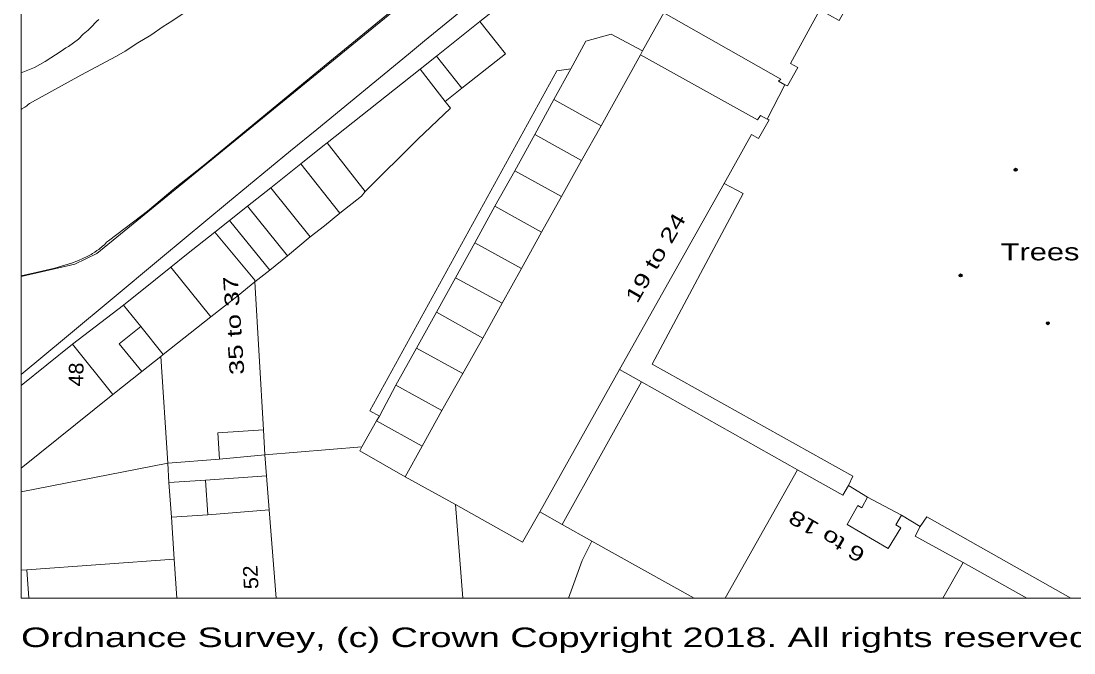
# Model space of a CAD drawing. Extents: x 528790 to 529292, y 179350 to 179856.
# Drawn here: x 528790.2 to 528898.3, y 179350.4 to 179415.2 of the extents above; entities that cross this region are included whole.
import ezdxf

# ---------------------------------------------------------------- set-up
doc = ezdxf.new("R2010")
doc.units = 0
doc.header["$LTSCALE"] = 0.6
doc.header["$PDMODE"] = 32
doc.header["$PDSIZE"] = 0.3
for name, color, linetype, lineweight in [('1', 7, 'Continuous', 13), ('2', 7, 'Continuous', 13), ('7', 7, 'Continuous', 13)]:
    doc.layers.add(name, color=color, linetype=linetype, lineweight=lineweight)
for name, color, linetype in [('3', 7, 'Continuous'), ('5', 7, 'Continuous'), ('8', 7, 'Continuous')]:
    doc.layers.add(name, color=color, linetype=linetype)

msp = doc.modelspace()

# ---------------------------------------------------------------- linework, layer by layer
at = {"layer": '1'}
for points in [[(528790.22, 179436.319), (528790.22, 179389.043), (528795.75, 179390.3), (528798, 179391.4), (528866.2, 179447.15)], [(528866.2, 179447.15), (528798, 179391.4), (528795.75, 179390.3), (528790.22, 179389.043), (528790.22, 179378.975), (528794.89, 179382.86), (528799.97, 179387.09), (528803.9, 179390.36), (528804.75, 179391.06), (528811.4, 179396.6), (528817.89, 179401.93), (528820.57, 179404.13), (528829.99, 179411.87), (528831.62, 179413.21), (528839.4, 179419.6)], [(528790.22, 179435.924), (528790.22, 179409.925), (528791.6, 179410.5), (528792.7, 179411.1), (528794.35, 179412.15), (528794.8, 179412.5), (528795.1, 179412.65), (528796.1, 179413.4), (528796.6, 179413.9), (528797.1, 179414.3), (528797.6, 179414.8), (528797.8, 179415.05), (528798, 179415.25), (528798.2, 179415.4)], [(528901.688, 179417.809), (528881.8, 179429), (528874.2, 179415.3), (528872.2, 179416.4), (528869.2, 179410.9), (528869.95, 179410.5), (528868.9, 179408.6), (528868.6, 179408.7), (528866.8, 179405.2), (528867, 179405.1), (528865.9, 179403.2), (528865.2, 179403.6), (528862.4, 179398.6), (528864.35, 179397.55), (528855, 179380.05), (528875.6, 179368.55), (528875.15, 179367.6), (528877.1, 179366.4), (528880.6, 179364.55), (528882.5, 179363.4), (528883.2, 179364.4), (528897.956, 179356.024), (528905.826, 179356.024)], [(528839.4, 179419.6), (528831.62, 179413.21), (528829.99, 179411.87), (528820.57, 179404.13), (528817.89, 179401.93), (528811.4, 179396.6), (528804.75, 179391.06), (528803.9, 179390.36), (528799.97, 179387.09), (528794.89, 179382.86), (528790.22, 179378.975), (528790.22, 179377.863), (528795.5, 179382.1), (528800.75, 179386.1), (528804.01, 179388.72), (528805.6, 179390), (528807.2, 179391.3), (528810.1, 179393.6), (528811.6, 179394.8), (528813.45, 179396.25), (528815.85, 179398.15), (528818.95, 179400.6), (528821.2, 179402.4), (528821.65, 179402.75), (528831.2, 179410.3), (528832.85, 179411.65), (528837.3, 179415.2), (528842.1, 179419)], [(528842.1, 179419), (528837.3, 179415.2), (528839.95, 179411.9), (528835.45, 179408.35), (528833.75, 179407), (528834.3, 179406.3), (528830.95, 179403.15), (528825.55, 179397.75), (528825.15, 179397.3), (528822.95, 179395.55), (528821.35, 179394.25), (528819.9, 179393.1), (528817.55, 179391.15), (528815.75, 179389.7), (528814.2, 179388.5), (528815.1, 179373.3), (528815.25, 179370.75), (528825.2, 179371.55), (528826.7, 179374.25), (528827, 179374.7), (528826, 179375.25), (528845.2, 179410.15), (528846.65, 179410.35), (528848.2, 179413.2), (528850.8, 179413.9), (528854, 179412.2), (528856.05, 179415.85)], [(528808.55, 179417.15), (528805.7, 179415.25), (528804.8, 179414.7), (528803.55, 179413.8), (528802.2, 179413), (528800.9, 179412.15), (528800, 179411.65), (528796.35, 179409.7), (528791.1, 179406.8), (528790.95, 179406.7), (528790.8, 179406.55), (528790.6, 179406.4), (528790.3, 179406.25), (528790.22, 179406.19), (528790.22, 179389.112), (528791.9, 179389.5), (528793.7, 179389.9), (528795.4, 179390.4), (528796.1, 179390.7), (528797, 179391.1), (528797.4, 179391.3), (528797.55, 179391.4), (528797.8, 179391.55), (528798, 179391.7), (528798.2, 179391.8), (528798.6, 179392.2), (528798.8, 179392.3), (528799, 179392.55), (528799.2, 179392.7), (528802.6, 179395.3), (528803.2, 179395.75), (528806, 179398.1), (528808.9, 179400.4), (528815.3, 179405.65), (528821.55, 179410.8), (528828.9, 179416.8)]]:
    msp.add_lwpolyline(points, dxfattribs=at)
for points in [[(528868.6, 179408.7), (528868.9, 179408.6), (528869.95, 179410.5), (528869.2, 179410.9), (528872.2, 179416.4), (528881.65, 179433.45), (528869.8, 179440.05), (528869.6, 179440.3), (528865.45, 179432.8), (528864.9, 179431.8), (528863.6, 179429.4), (528862.95, 179428.25), (528862.35, 179427.15), (528860.2, 179423.3), (528856.2, 179416.1), (528868.2, 179409.3), (528867.95, 179409.1)], [(528853.8, 179411.8), (528865.8, 179405.1), (528866.1, 179405.55), (528866.8, 179405.2), (528868.6, 179408.7), (528867.95, 179409.1), (528868.2, 179409.3), (528856.2, 179416.1), (528856.05, 179415.85), (528854, 179412.2)], [(528837.3, 179415.2), (528832.85, 179411.65), (528835.45, 179408.35), (528839.95, 179411.9)], [(528853.8, 179411.8), (528854, 179412.2), (528850.8, 179413.9), (528848.2, 179413.2), (528846.65, 179410.35), (528844.9, 179407.2), (528849.75, 179404.5)], [(528841.6, 179389.85), (528839.6, 179386.3), (528837.6, 179382.7), (528835.55, 179379.1), (528833.4, 179375.3), (528831.4, 179371.65), (528829.65, 179368.5), (528834.8, 179365.65), (528841.7, 179361.8), (528843.45, 179364.9), (528851.65, 179379.5), (528862.4, 179398.6), (528865.2, 179403.6), (528865.9, 179403.2), (528867, 179405.1), (528866.8, 179405.2), (528866.1, 179405.55), (528865.8, 179405.1), (528853.8, 179411.8), (528849.75, 179404.5), (528847.75, 179400.95), (528845.7, 179397.25), (528843.65, 179393.6)], [(528831.2, 179410.3), (528833.75, 179407), (528835.45, 179408.35), (528832.85, 179411.65)], [(528821.65, 179402.75), (528825.55, 179397.75), (528830.95, 179403.15), (528834.3, 179406.3), (528833.75, 179407), (528831.2, 179410.3)], [(528834.8, 179388.9), (528836.8, 179392.5), (528838.85, 179396.25), (528840.9, 179399.9), (528842.95, 179403.6), (528844.9, 179407.2), (528846.65, 179410.35), (528845.2, 179410.15), (528826, 179375.25), (528827, 179374.7), (528828.7, 179377.9), (528830.8, 179381.7), (528832.85, 179385.4)], [(528844.9, 179407.2), (528842.95, 179403.6), (528847.75, 179400.95), (528849.75, 179404.5)], [(528847.75, 179400.95), (528842.95, 179403.6), (528840.9, 179399.9), (528845.7, 179397.25)], [(528825.55, 179397.75), (528821.65, 179402.75), (528821.2, 179402.4), (528818.95, 179400.6), (528822.95, 179395.55), (528825.15, 179397.3)], [(528822.95, 179395.55), (528818.95, 179400.6), (528815.85, 179398.15), (528819.9, 179393.1), (528821.35, 179394.25)], [(528845.7, 179397.25), (528840.9, 179399.9), (528838.85, 179396.25), (528843.65, 179393.6)], [(528813.45, 179396.25), (528817.55, 179391.15), (528819.9, 179393.1), (528815.85, 179398.15)], [(528851.65, 179379.5), (528853.9, 179378.25), (528869.9, 179369.2), (528874.55, 179366.6), (528875.15, 179367.6), (528875.6, 179368.55), (528855, 179380.05), (528864.35, 179397.55), (528862.4, 179398.6)], [(528811.6, 179394.8), (528815.75, 179389.7), (528817.55, 179391.15), (528813.45, 179396.25)], [(528843.65, 179393.6), (528838.85, 179396.25), (528836.8, 179392.5), (528841.6, 179389.85)], [(528810.1, 179393.6), (528814.2, 179388.65), (528814.2, 179388.5), (528815.75, 179389.7), (528811.6, 179394.8)], [(528805.6, 179390), (528809.7, 179384.9), (528812.5, 179387.1), (528814.2, 179388.5), (528814.2, 179388.65), (528810.1, 179393.6), (528807.2, 179391.3)], [(528841.6, 179389.85), (528836.8, 179392.5), (528834.8, 179388.9), (528839.6, 179386.3)], [(528809.7, 179384.9), (528805.6, 179390), (528804.01, 179388.72), (528800.75, 179386.1), (528802.5, 179383.9), (528804.8, 179381.05)], [(528810.6, 179370.3), (528810.4, 179373), (528815.1, 179373.3), (528814.2, 179388.5), (528812.5, 179387.1), (528809.7, 179384.9), (528804.8, 179381.05), (528804.55, 179380.85), (528805.3, 179369.9)], [(528832.85, 179385.4), (528837.6, 179382.7), (528839.6, 179386.3), (528834.8, 179388.9)], [(528802.6, 179379.3), (528800.3, 179382.15), (528802.5, 179383.9), (528800.75, 179386.1), (528795.5, 179382.1), (528799.65, 179376.95)], [(528837.6, 179382.7), (528832.85, 179385.4), (528830.8, 179381.7), (528835.55, 179379.1)], [(528804.8, 179381.05), (528802.5, 179383.9), (528800.3, 179382.15), (528802.6, 179379.3), (528804.55, 179380.85)], [(528790.22, 179377.863), (528790.22, 179369.383), (528799.65, 179376.95), (528795.5, 179382.1)], [(528790.22, 179366.934), (528805.3, 179369.9), (528804.55, 179380.85), (528802.6, 179379.3), (528799.65, 179376.95), (528790.22, 179369.383)], [(528835.55, 179379.1), (528830.8, 179381.7), (528828.7, 179377.9), (528833.4, 179375.3)], [(528843.45, 179364.9), (528845.75, 179363.6), (528853.9, 179378.25), (528851.65, 179379.5)], [(528828.7, 179377.9), (528827, 179374.7), (528826.7, 179374.25), (528831.4, 179371.65), (528833.4, 179375.3)], [(528859.31, 179356.024), (528862.494, 179356.024), (528869.9, 179369.2), (528853.9, 179378.25), (528845.75, 179363.6), (528848.8, 179361.9)], [(528815.25, 179370.75), (528815.1, 179373.3), (528810.4, 179373), (528810.6, 179370.3)], [(528831.4, 179371.65), (528826.7, 179374.25), (528825.2, 179371.55), (528825, 179371.15), (528829.65, 179368.5)], [(528816.418, 179356.024), (528835.563, 179356.024), (528834.8, 179365.65), (528829.65, 179368.5), (528825, 179371.15), (528825.2, 179371.55), (528815.25, 179370.75), (528815.4, 179368.6), (528815.7, 179365.1)], [(528805.3, 179369.9), (528805.4, 179367.9), (528809.15, 179368.15), (528815.4, 179368.6), (528815.25, 179370.75), (528810.6, 179370.3)], [(528790.22, 179366.934), (528790.22, 179358.915), (528790.8, 179358.95), (528805.95, 179360.05), (528805.65, 179364.35), (528805.4, 179367.9), (528805.3, 179369.9)], [(528862.494, 179356.024), (528884.841, 179356.024), (528886.9, 179359.7), (528882, 179362.4), (528882.5, 179363.4), (528880.6, 179364.55), (528880, 179363.55), (528880.5, 179363.25), (528879.2, 179361.15), (528875, 179363.6), (528876.1, 179365.55), (528876.5, 179365.3), (528877.1, 179366.4), (528875.15, 179367.6), (528874.55, 179366.6), (528869.9, 179369.2)], [(528809.4, 179364.6), (528809.15, 179368.15), (528805.4, 179367.9), (528805.65, 179364.35)], [(528815.4, 179368.6), (528809.15, 179368.15), (528809.4, 179364.6), (528815.7, 179365.1)], [(528880.6, 179364.55), (528877.1, 179366.4), (528876.5, 179365.3), (528876.1, 179365.55), (528875, 179363.6), (528879.2, 179361.15), (528880.5, 179363.25), (528880, 179363.55)], [(528816.418, 179356.024), (528815.7, 179365.1), (528809.4, 179364.6), (528805.65, 179364.35), (528805.95, 179360.05), (528806.195, 179356.024)], [(528846.412, 179356.024), (528847.8, 179359.9), (528848.8, 179361.9), (528845.75, 179363.6), (528843.45, 179364.9), (528841.7, 179361.8), (528834.8, 179365.65), (528835.563, 179356.024)], [(528893.463, 179356.024), (528897.956, 179356.024), (528883.2, 179364.4), (528882.5, 179363.4), (528882, 179362.4), (528886.9, 179359.7)], [(528859.31, 179356.024), (528848.8, 179361.9), (528847.8, 179359.9), (528846.412, 179356.024)], [(528791.01, 179356.024), (528806.195, 179356.024), (528805.95, 179360.05), (528790.8, 179358.95)], [(528893.463, 179356.024), (528886.9, 179359.7), (528884.841, 179356.024)], [(528791.01, 179356.024), (528790.8, 179358.95), (528790.22, 179358.915), (528790.22, 179356.024)]]:
    msp.add_lwpolyline(points, close=True, dxfattribs=at)
at = {"layer": '2'}
for p, q in [((528837.3, 179415.2), (528842.1, 179419)), ((528854, 179412.2), (528856.05, 179415.85)), ((528837.3, 179415.2), (528832.85, 179411.65)), ((528854, 179412.2), (528853.8, 179411.8)), ((528832.85, 179411.65), (528831.2, 179410.3)), ((528832.85, 179411.65), (528835.45, 179408.35)), ((528849.75, 179404.5), (528853.8, 179411.8)), ((528831.2, 179410.3), (528821.65, 179402.75)), ((528831.2, 179410.3), (528833.75, 179407)), ((528844.9, 179407.2), (528846.65, 179410.35)), ((528833.75, 179407), (528835.45, 179408.35)), ((528866.8, 179405.2), (528868.6, 179408.7)), ((528842.95, 179403.6), (528844.9, 179407.2)), ((528849.75, 179404.5), (528844.9, 179407.2)), ((528840.9, 179399.9), (528842.95, 179403.6)), ((528842.95, 179403.6), (528847.75, 179400.95)), ((528847.75, 179400.95), (528849.75, 179404.5)), ((528821.65, 179402.75), (528825.55, 179397.75)), ((528818.95, 179400.6), (528815.85, 179398.15)), ((528818.95, 179400.6), (528822.95, 179395.55)), ((528845.7, 179397.25), (528847.75, 179400.95)), ((528838.85, 179396.25), (528840.9, 179399.9)), ((528845.7, 179397.25), (528840.9, 179399.9)), ((528815.85, 179398.15), (528813.45, 179396.25)), ((528815.85, 179398.15), (528819.9, 179393.1)), ((528862.4, 179398.6), (528851.65, 179379.5)), ((528843.65, 179393.6), (528845.7, 179397.25)), ((528813.45, 179396.25), (528811.6, 179394.8)), ((528813.45, 179396.25), (528817.55, 179391.15)), ((528836.8, 179392.5), (528838.85, 179396.25)), ((528838.85, 179396.25), (528843.65, 179393.6)), ((528811.6, 179394.8), (528810.1, 179393.6)), ((528811.6, 179394.8), (528815.75, 179389.7)), ((528817.55, 179391.15), (528819.9, 179393.1)), ((528841.6, 179389.85), (528843.65, 179393.6)), ((528834.8, 179388.9), (528836.8, 179392.5)), ((528841.6, 179389.85), (528836.8, 179392.5)), ((528815.75, 179389.7), (528817.55, 179391.15)), ((528805.6, 179390), (528809.7, 179384.9)), ((528814.2, 179388.5), (528815.75, 179389.7)), ((528839.6, 179386.3), (528841.6, 179389.85)), ((528814.2, 179388.5), (528815.1, 179373.3)), ((528832.85, 179385.4), (528834.8, 179388.9)), ((528834.8, 179388.9), (528839.6, 179386.3)), ((528837.6, 179382.7), (528839.6, 179386.3)), ((528795.5, 179382.1), (528800.75, 179386.1)), ((528802.5, 179383.9), (528800.75, 179386.1)), ((528830.8, 179381.7), (528832.85, 179385.4)), ((528837.6, 179382.7), (528832.85, 179385.4)), ((528804.8, 179381.05), (528809.7, 179384.9)), ((528804.8, 179381.05), (528802.5, 179383.9)), ((528790.22, 179377.863), (528795.5, 179382.1)), ((528795.5, 179382.1), (528799.65, 179376.95)), ((528835.55, 179379.1), (528837.6, 179382.7)), ((528804.55, 179380.85), (528802.6, 179379.3)), ((528804.8, 179381.05), (528804.55, 179380.85)), ((528804.55, 179380.85), (528805.3, 179369.9)), ((528828.7, 179377.9), (528830.8, 179381.7)), ((528830.8, 179381.7), (528835.55, 179379.1)), ((528802.6, 179379.3), (528799.65, 179376.95)), ((528833.4, 179375.3), (528835.55, 179379.1)), ((528851.65, 179379.5), (528843.45, 179364.9)), ((528851.65, 179379.5), (528853.9, 179378.25)), ((528827, 179374.7), (528828.7, 179377.9)), ((528833.4, 179375.3), (528828.7, 179377.9)), ((528853.9, 179378.25), (528845.75, 179363.6)), ((528853.9, 179378.25), (528869.9, 179369.2)), ((528799.65, 179376.95), (528790.22, 179369.383)), ((528826.7, 179374.25), (528827, 179374.7)), ((528831.4, 179371.65), (528833.4, 179375.3)), ((528815.1, 179373.3), (528815.25, 179370.75)), ((528825.2, 179371.55), (528826.7, 179374.25)), ((528826.7, 179374.25), (528831.4, 179371.65)), ((528815.25, 179370.75), (528825.2, 179371.55)), ((528829.65, 179368.5), (528831.4, 179371.65)), ((528805.3, 179369.9), (528810.6, 179370.3)), ((528810.6, 179370.3), (528815.25, 179370.75)), ((528815.4, 179368.6), (528815.25, 179370.75)), ((528790.22, 179366.934), (528805.3, 179369.9)), ((528805.3, 179369.9), (528805.4, 179367.9)), ((528869.9, 179369.2), (528862.494, 179356.024)), ((528805.4, 179367.9), (528809.15, 179368.15)), ((528805.4, 179367.9), (528805.65, 179364.35)), ((528809.15, 179368.15), (528815.4, 179368.6)), ((528809.15, 179368.15), (528809.4, 179364.6)), ((528815.7, 179365.1), (528815.4, 179368.6)), ((528834.8, 179365.65), (528829.65, 179368.5)), ((528875.15, 179367.6), (528877.1, 179366.4)), ((528877.1, 179366.4), (528880.6, 179364.55)), ((528809.4, 179364.6), (528815.7, 179365.1)), ((528816.418, 179356.024), (528815.7, 179365.1)), ((528834.8, 179365.65), (528835.563, 179356.024)), ((528845.75, 179363.6), (528843.45, 179364.9)), ((528805.65, 179364.35), (528809.4, 179364.6)), ((528805.65, 179364.35), (528805.95, 179360.05)), ((528848.8, 179361.9), (528845.75, 179363.6)), ((528880.6, 179364.55), (528882.5, 179363.4)), ((528859.31, 179356.024), (528848.8, 179361.9)), ((528805.95, 179360.05), (528790.8, 179358.95)), ((528805.95, 179360.05), (528806.195, 179356.024)), ((528886.9, 179359.7), (528884.841, 179356.024)), ((528886.9, 179359.7), (528893.463, 179356.024)), ((528790.8, 179358.95), (528790.22, 179358.915)), ((528791.01, 179356.024), (528790.8, 179358.95))]:
    msp.add_line(p, q, dxfattribs=at)
for points in [[(528906.55, 179446.2), (528898.1, 179448.9), (528889.7, 179451.6), (528884.6, 179453.25), (528882.9, 179453.7), (528881.15, 179454), (528880.3, 179454.1), (528879.5, 179454.15), (528878.6, 179454.2), (528877.8, 179454.15), (528876.8, 179453.9), (528875.8, 179453.7), (528874.9, 179453.3), (528873.2, 179452.55), (528871.6, 179451.55), (528870.2, 179450.55), (528868.8, 179449.5), (528867.4, 179448.3), (528866.2, 179447.15), (528798, 179391.4), (528795.75, 179390.3), (528790.22, 179389.043)], [(528842.1, 179419), (528842, 179419.25), (528841.8, 179419.5), (528841.6, 179419.7), (528841.3, 179419.8), (528840.5, 179419.8), (528839.95, 179419.75), (528839.4, 179419.6), (528831.62, 179413.21), (528829.99, 179411.87), (528820.57, 179404.13), (528817.89, 179401.93), (528811.4, 179396.6), (528804.75, 179391.06), (528803.9, 179390.36), (528799.97, 179387.09), (528794.89, 179382.86), (528790.22, 179378.975)], [(528790.22, 179406.19), (528790.3, 179406.25), (528790.6, 179406.4), (528790.8, 179406.55), (528790.95, 179406.7), (528791.1, 179406.8), (528796.35, 179409.7), (528800, 179411.65), (528800.9, 179412.15), (528802.2, 179413), (528803.55, 179413.8), (528804.8, 179414.7), (528805.7, 179415.25), (528808.55, 179417.15)], [(528790.22, 179389.112), (528791.9, 179389.5), (528793.7, 179389.9), (528795.4, 179390.4), (528796.1, 179390.7), (528797, 179391.1), (528797.4, 179391.3), (528797.55, 179391.4), (528797.8, 179391.55), (528798, 179391.7), (528798.2, 179391.8), (528798.6, 179392.2), (528798.8, 179392.3), (528799, 179392.55), (528799.2, 179392.7), (528802.6, 179395.3), (528803.2, 179395.75), (528806, 179398.1), (528808.9, 179400.4), (528815.3, 179405.65), (528821.55, 179410.8), (528828.9, 179416.8)], [(528868.6, 179408.7), (528867.95, 179409.1), (528868.2, 179409.3), (528856.2, 179416.1)], [(528872.2, 179416.4), (528869.2, 179410.9), (528869.95, 179410.5), (528868.9, 179408.6), (528868.6, 179408.7)], [(528798.2, 179415.4), (528798, 179415.25), (528797.8, 179415.05), (528797.6, 179414.8), (528797.1, 179414.3), (528796.6, 179413.9), (528796.1, 179413.4), (528795.1, 179412.65), (528794.8, 179412.5), (528794.35, 179412.15), (528792.7, 179411.1), (528791.6, 179410.5), (528790.22, 179409.925)], [(528835.45, 179408.35), (528839.95, 179411.9), (528837.3, 179415.2)], [(528846.65, 179410.35), (528848.2, 179413.2), (528850.8, 179413.9), (528854, 179412.2)], [(528853.8, 179411.8), (528865.8, 179405.1), (528866.1, 179405.55), (528866.8, 179405.2)], [(528827, 179374.7), (528826, 179375.25), (528845.2, 179410.15), (528846.65, 179410.35)], [(528825.55, 179397.75), (528830.95, 179403.15), (528834.3, 179406.3), (528833.75, 179407)], [(528866.8, 179405.2), (528867, 179405.1), (528865.9, 179403.2), (528865.2, 179403.6), (528862.4, 179398.6)], [(528821.65, 179402.75), (528821.2, 179402.4), (528818.95, 179400.6)], [(528862.4, 179398.6), (528864.35, 179397.55), (528855, 179380.05), (528875.6, 179368.55), (528875.15, 179367.6)], [(528822.95, 179395.55), (528825.15, 179397.3), (528825.55, 179397.75)], [(528819.9, 179393.1), (528821.35, 179394.25), (528822.95, 179395.55)], [(528810.1, 179393.6), (528807.2, 179391.3), (528805.6, 179390)], [(528810.1, 179393.6), (528814.2, 179388.65), (528814.2, 179388.5)], [(528805.6, 179390), (528804.01, 179388.72), (528800.75, 179386.1)], [(528809.7, 179384.9), (528812.5, 179387.1), (528814.2, 179388.5)], [(528802.5, 179383.9), (528800.3, 179382.15), (528802.6, 179379.3)], [(528815.1, 179373.3), (528810.4, 179373), (528810.6, 179370.3)], [(528829.65, 179368.5), (528825, 179371.15), (528825.2, 179371.55)], [(528869.9, 179369.2), (528874.55, 179366.6), (528875.15, 179367.6)], [(528877.1, 179366.4), (528876.5, 179365.3), (528876.1, 179365.55), (528875, 179363.6), (528879.2, 179361.15), (528880.5, 179363.25), (528880, 179363.55), (528880.6, 179364.55)], [(528843.45, 179364.9), (528841.7, 179361.8), (528834.8, 179365.65)], [(528882.5, 179363.4), (528883.2, 179364.4), (528897.956, 179356.024)], [(528882.5, 179363.4), (528882, 179362.4), (528886.9, 179359.7)], [(528846.412, 179356.024), (528847.8, 179359.9), (528848.8, 179361.9)]]:
    msp.add_lwpolyline(points, dxfattribs=at)
at = {"layer": '3'}
for p in [(528892.3, 179400), (528886.65, 179389.15), (528895.6, 179384.25)]:
    msp.add_point(p, dxfattribs=at)
at = {"layer": '7'}
msp.add_lwpolyline([(528790.22, 179356.024), (529290.22, 179356.024), (529290.22, 179856.024), (528790.22, 179856.024)], close=True, dxfattribs=at)

# ---------------------------------------------------------------- texts
at = {"layer": '5'}
for s, rotation, width, p in [('19 to 24', 60, 1.4, (528853.45, 179386.2)), ('35 to 37', 94, 1.4, (528813.15, 179379)), ('48', 89, 1.1, (528796.6, 179377.75)), ('6 to 18', 150, 1.4, (528877, 179360.9)), ('52', 93, 1.1, (528814.6, 179357))]:
    msp.add_text(s, height=1.5, rotation=rotation, dxfattribs=dict(at, width=width)).set_placement(p)
at = {"layer": '5', "width": 1.35}
msp.add_text('Trees', height=1.75, dxfattribs=at).set_placement((528890.77, 179390.7))
at = {"layer": '8', "width": 1.45}
msp.add_text('Ordnance Survey, (c) Crown Copyright 2018. All rights reserved. Licence number 100022432', height=2, dxfattribs=at).set_placement((528790.22, 179351.024))

doc.saveas('drawing.dxf')
